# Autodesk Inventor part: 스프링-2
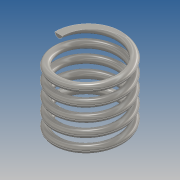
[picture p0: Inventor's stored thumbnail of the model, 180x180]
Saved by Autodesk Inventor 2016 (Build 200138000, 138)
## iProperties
Created: 2016-03
Part Number: 스프링-2
Material: 스테인레스 스틸
Document SubType Name: Modeling
Designer: Administrator
Density: 8 g/cm^3
Appearance: 반연마
Mass: 6.54743 g
Surface Area: 16.696 cm^2
Volume: 0.818429 cm^3
Author: Administrator
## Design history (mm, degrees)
sketch "스케치1"
  geometry: L1 (0, 0)-(8.5, 0); L2 (8.5, 0)-(8.5, 17.5); L3 (8.5, 17.5)-(0, 17.5); L4 (0, 17.5)-(0, 0); C1 r 1 at (8.5, 0)
  constraints: 8 end point, 2 parallel, 1 centre point, 1 coincident, 1 horizontal, 1 perpendicular
  dimensions: "d0" = 17.5 distance of L1.end L2.end (derived); "d1" = 17 diameter of L2 L4; "d2" = 2 diameter of C1
feature "코일1" pitch "d3" = 10; turns "d5" = 5; dims "d4" = 17.5 (= d0), "d6" = 0, angle "d7" = 90 deg, angle "d8" = 90 deg, "d9" = 0, "d10" = 0
sketch "스케치2"
  geometry: L1 (4.1, 0)-(-21.424, 0); L2 (-21.424, 0)-(-21.424, -13.495); L3 (-21.424, -13.495)-(4.1, -13.495); L4 (4.1, -13.495)-(4.1, 0); 3 further points
  constraints: 8 end point, 2 parallel, 1 horizontal, 1 horizontal alignment, 1 perpendicular, 1 point on line
extrude "돌출1" cut sketch "스케치2" stored distance "d11" = 0; taper "d12" = 0 deg
sketch "스케치3"
  geometry: L1 (-2.819, 0)-(17.433, 0); L2 (17.433, 0)-(17.433, 5.421); L3 (17.433, 5.421)-(-2.819, 5.421); L4 (-2.819, 5.421)-(-2.819, 0); 3 further points
  constraints: 8 end point, 2 parallel, 1 horizontal, 1 horizontal alignment, 1 perpendicular, 1 point on line
extrude "돌출2" cut sketch "스케치3" stored distance "d13" = 0; taper "d14" = 0 deg
node "솔리드1"
